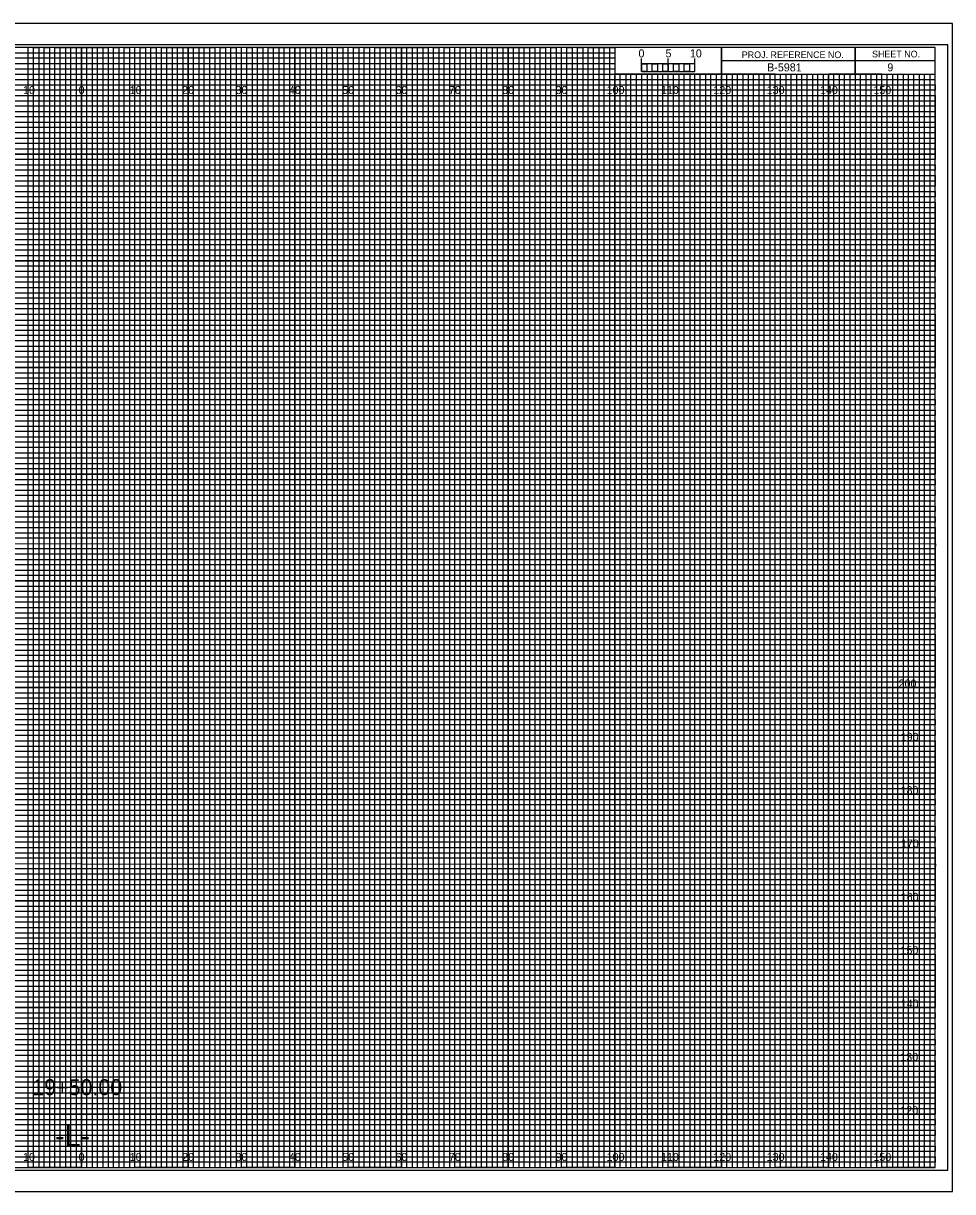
# Model space of a CAD drawing. Extents: x -13 to 323, y -5 to 1754.
# Drawn here: x 149.1 to 323.3, y 1095.5 to 1314.5 of the extents above; entities that cross this region are included whole.
import ezdxf

# ---------------------------------------------------------------- set-up
doc = ezdxf.new("R2010")
doc.units = 0
for name, color, linetype in [('Exist Cross Section Cell', 7, 'Continuous'), ('Exist XS Center Line Elevation Label', 7, 'Continuous'), ('Exist XS Ground Line', 7, 'Continuous'), ('Prop CMT Concrete Structures', 7, 'Continuous'), ('Prop CMT Guardrail Graphics', 7, 'Continuous'), ('Prop CMT Pvmt Course 1', 7, 'Continuous'), ('Prop CMT Pvmt Course 2', 7, 'Continuous'), ('Prop CMT Pvmt Course 3', 7, 'Continuous'), ('Prop CMT Pvmt Surface', 7, 'Continuous'), ('Prop CMT Shld Paved Course 1', 7, 'Continuous'), ('Prop CMT Shld Paved Course 2', 7, 'Continuous'), ('Prop CMT Shld Paved Course 3', 7, 'Continuous'), ('Prop CMT Subgrade Earthwork', 7, 'Continuous'), ('Prop XS Ditch Standard Text', 7, 'Continuous'), ('Prop XS SE Text', 7, 'Continuous'), ('Prop XS Side Slope Text', 7, 'Continuous'), ('Scratch_Level_0', 7, 'Continuous')]:
    doc.layers.add(name, color=color, linetype=linetype)

msp = doc.modelspace()

# ---------------------------------------------------------------- linework, layer by layer
at = {"layer": 'Exist XS Center Line Elevation Label'}
for points in [[(145, 1100), (155, 1100), (155, 1310), (165, 1310), (165, 1100), (175, 1100), (175, 1310), (185, 1310), (185, 1100), (195, 1100), (195, 1310), (205, 1310), (205, 1100), (215, 1100), (215, 1310), (225, 1310), (225, 1100), (235, 1100), (235, 1310), (245, 1310), (245, 1100), (255, 1100), (255, 1310), (259.93, 1310), (260, 1310), (260, 1305), (264.99, 1305), (264.99, 1100), (275, 1100), (275, 1305), (285, 1305), (285, 1100), (295, 1100), (295, 1305), (305, 1305), (305, 1100), (315, 1100), (315, 1305)], [(0, 1305), (275, 1305)], [(0, 1285), (320, 1285), (320, 1295), (0, 1295)], [(0, 1265), (320, 1265), (320, 1275), (0, 1275)], [(0, 1245), (320, 1245), (320, 1255), (0, 1255)], [(0, 1225), (320, 1225), (320, 1235), (0, 1235)], [(0, 1205), (320, 1205), (320, 1215), (0, 1215)], [(0, 1185), (320, 1185), (320, 1195), (0, 1195)], [(0, 1165), (320, 1165), (320, 1175), (0, 1175)], [(0, 1145), (320, 1145), (320, 1155), (0, 1155)], [(0, 1125), (320, 1125), (320, 1135), (0, 1135)], [(0, 1105), (320, 1105), (320, 1115), (0, 1115)]]:
    msp.add_lwpolyline(points, dxfattribs=at)
at = {"layer": 'Exist XS Ground Line'}
for p, q in [((150, 1310), (140, 1310)), ((150, 1100), (150, 1310)), ((170, 1310), (160, 1310)), ((160, 1310), (160, 1100)), ((170, 1100), (170, 1310)), ((190, 1310), (180, 1310)), ((180, 1310), (180, 1100)), ((190, 1100), (190, 1310)), ((210, 1310), (200, 1310)), ((200, 1310), (200, 1100)), ((210, 1100), (210, 1310)), ((230, 1310), (220, 1310)), ((220, 1310), (220, 1100)), ((230, 1100), (230, 1310)), ((250, 1310), (240, 1310)), ((240, 1310), (240, 1100)), ((250, 1100), (250, 1310)), ((260, 1310), (260, 1100)), ((270, 1100), (270, 1305)), ((290, 1305), (280, 1305)), ((280, 1305), (280, 1100)), ((290, 1100), (290, 1305)), ((310, 1305), (300, 1305)), ((300, 1305), (300, 1100)), ((310, 1100), (310, 1305)), ((160, 1100), (150, 1100)), ((180, 1100), (170, 1100)), ((200, 1100), (190, 1100)), ((220, 1100), (210, 1100)), ((240, 1100), (230, 1100)), ((260, 1100), (250, 1100)), ((280, 1100), (270, 1100)), ((300, 1100), (290, 1100)), ((320, 1100), (310, 1100)), ((320, 1100), (320, 1100))]:
    msp.add_line(p, q, dxfattribs=at)
for points in [[(0, 1300), (320, 1300), (320, 1290), (0, 1290)], [(0, 1280), (320, 1280), (320, 1270), (0, 1270)], [(0, 1260), (320, 1260), (320, 1250), (0, 1250)], [(0, 1240), (320, 1240), (320, 1230), (0, 1230)], [(0, 1220), (320, 1220), (320, 1210), (0, 1210)], [(0, 1200), (320, 1200), (320, 1190), (0, 1190)], [(0, 1180), (320, 1180), (320, 1170), (0, 1170)], [(0, 1160), (320, 1160), (320, 1150), (0, 1150)], [(0, 1140), (320, 1140), (320, 1130), (0, 1130)], [(0, 1120), (320, 1120), (320, 1110), (0, 1110)]]:
    msp.add_lwpolyline(points, dxfattribs=at)
at = {"layer": 'Prop CMT Pvmt Course 1'}
for p, q in [((323.3, 1314.5), (-13.4, 1314.5)), ((-13.4, 1095.5), (323.3, 1095.5))]:
    msp.add_line(p, q, dxfattribs=at)
at = {"layer": 'Prop CMT Pvmt Course 2'}
msp.add_lwpolyline([(-13.4, 1095.5), (323.3, 1095.5), (323.3, 1314.5), (-13.4, 1314.5)], close=True, dxfattribs=at)
at = {"layer": 'Prop CMT Pvmt Course 3'}
msp.add_lwpolyline([(-10.8, 1099.5), (322.4, 1099.5), (322.4, 1310.5), (-10.8, 1310.5)], close=True, dxfattribs=at)
at = {"layer": 'Prop CMT Shld Paved Course 1'}
for p, q in [((305, 1310), (305, 1305)), ((305, 1305), (305, 1310)), ((280, 1307.5), (280, 1305)), ((320, 1307.49), (280, 1307.49)), ((280, 1305), (320, 1305))]:
    msp.add_line(p, q, dxfattribs=at)
for points in [[(320, 1310), (0, 1310), (0, 1100), (320, 1100)], [(280, 1310), (260, 1310), (260, 1305.03), (280, 1305.03)], [(320, 1310), (280, 1310), (280, 1305), (320, 1305)]]:
    msp.add_lwpolyline(points, close=True, dxfattribs=at)
at = {"layer": 'Prop CMT Shld Paved Course 2'}
for p, q in [((267, 1305), (266.01, 1305)), ((266.01, 1305), (266.01, 1100)), ((267, 1100), (267, 1305)), ((269, 1305), (268, 1305)), ((268, 1305), (268, 1100)), ((269, 1100), (269, 1305)), ((266.01, 1100), (265, 1100)), ((268, 1100), (267, 1100))]:
    msp.add_line(p, q, dxfattribs=at)
for points in [[(150, 1100), (151, 1100), (151, 1310), (152, 1310), (152, 1100)], [(152, 1100), (153, 1100), (153, 1310), (154, 1310), (154, 1100)], [(155, 1100), (156, 1100), (156, 1310), (157, 1310), (157, 1100)], [(157, 1100), (158, 1100), (158, 1310), (159, 1310), (159, 1100)], [(160, 1100), (161, 1100), (161, 1310), (162, 1310), (162, 1100)], [(162, 1100), (163, 1100), (163, 1310), (164, 1310), (164, 1100)], [(165, 1100), (166, 1100), (166, 1310), (167, 1310), (167, 1100)], [(167, 1100), (168, 1100), (168, 1310), (169, 1310), (169, 1100)], [(170, 1100), (171, 1100), (171, 1310), (172, 1310), (172, 1100)], [(172, 1100), (173, 1100), (173, 1310), (174, 1310), (174, 1100)], [(175, 1100), (176, 1100), (176, 1310), (177, 1310), (177, 1100)], [(177, 1100), (178, 1100), (178, 1310), (179, 1310), (179, 1100)], [(180, 1100), (181, 1100), (181, 1310), (182, 1310), (182, 1100)], [(182, 1100), (183, 1100), (183, 1310), (184, 1310), (184, 1100)], [(185, 1100), (186, 1100), (186, 1310), (187, 1310), (187, 1100)], [(187, 1100), (188, 1100), (188, 1310), (189, 1310), (189, 1100)], [(190, 1100), (191, 1100), (191, 1310), (192, 1310), (192, 1100)], [(192, 1100), (193, 1100), (193, 1310), (194, 1310), (194, 1100)], [(195, 1100), (196, 1100), (196, 1310), (197, 1310), (197, 1100)], [(197, 1100), (198, 1100), (198, 1310), (199, 1310), (199, 1100)], [(200, 1100), (201, 1100), (201, 1310), (202, 1310), (202, 1100)], [(202, 1100), (203, 1100), (203, 1310), (204, 1310), (204, 1100)], [(205, 1100), (206, 1100), (206, 1310), (207, 1310), (207, 1100)], [(207, 1100), (208, 1100), (208, 1310), (209, 1310), (209, 1100)], [(210, 1100), (211, 1100), (211, 1310), (212, 1310), (212, 1100)], [(212, 1100), (213, 1100), (213, 1310), (214, 1310), (214, 1100)], [(215, 1100), (216, 1100), (216, 1310), (217, 1310), (217, 1100)], [(217, 1100), (218, 1100), (218, 1310), (219, 1310), (219, 1100)], [(220, 1100), (221, 1100), (221, 1310), (222, 1310), (222, 1100)], [(222, 1100), (223, 1100), (223, 1310), (224, 1310), (224, 1100)], [(225, 1100), (226, 1100), (226, 1310), (227, 1310), (227, 1100)], [(227, 1100), (228, 1100), (228, 1310), (229, 1310), (229, 1100)], [(230, 1100), (231, 1100), (231, 1310), (232, 1310), (232, 1100)], [(232, 1100), (233, 1100), (233, 1310), (234, 1310), (234, 1100)], [(235, 1100), (236, 1100), (236, 1310), (237, 1310), (237, 1100)], [(237, 1100), (238, 1100), (238, 1310), (239, 1310), (239, 1100)], [(240, 1100), (241, 1100), (241, 1310), (242, 1310), (242, 1100)], [(242, 1100), (243, 1100), (243, 1310), (244, 1310), (244, 1100)], [(245, 1100), (246, 1100), (246, 1310), (247, 1310), (247, 1100)], [(247, 1100), (248, 1100), (248, 1310), (249, 1310), (249, 1100)], [(250, 1100), (251, 1100), (251, 1310), (252, 1310), (252, 1100)], [(252, 1100), (253, 1100), (253, 1310), (254, 1310), (254, 1100)], [(255, 1100), (256, 1100), (256, 1310), (257, 1310), (257, 1100)], [(257, 1100), (258, 1100), (258, 1310), (259, 1310), (259, 1100)], [(260, 1100), (261, 1100), (261, 1305), (262.02, 1305), (262.02, 1100)], [(262, 1100), (263, 1100), (263, 1305), (263.99, 1305), (263.99, 1100)], [(270, 1100), (270.98, 1100), (270.98, 1305), (272, 1305), (272, 1100)], [(272, 1100), (273, 1100), (273, 1305), (274.05, 1305), (274.05, 1100)], [(275, 1100), (276, 1100), (276, 1305), (277, 1305), (277, 1100)], [(277, 1100), (278, 1100), (278, 1305), (279, 1305), (279, 1100)], [(280, 1100), (281, 1100), (281, 1305), (282, 1305), (282, 1100)], [(282, 1100), (283, 1100), (283, 1305), (284, 1305), (284, 1100)], [(285, 1100), (286, 1100), (286, 1305), (287, 1305), (287, 1100)], [(287, 1100), (288, 1100), (288, 1305), (289, 1305), (289, 1100)], [(290, 1100), (291, 1100), (291, 1305), (292, 1305), (292, 1100)], [(292, 1100), (293, 1100), (293, 1305), (294, 1305), (294, 1100)], [(295, 1100), (296, 1100), (296, 1305), (297, 1305), (297, 1100)], [(297, 1100), (298, 1100), (298, 1305), (299, 1305), (299, 1100)], [(300, 1100), (301, 1100), (301, 1305), (302, 1305), (302, 1100)], [(302, 1100), (303, 1100), (303, 1305), (304, 1305), (304, 1100)], [(305, 1100), (306, 1100), (306, 1305), (307, 1305), (307, 1100)], [(307, 1100), (308, 1100), (308, 1305), (309, 1305), (309, 1100)], [(310, 1100), (311, 1100), (311, 1305), (312, 1305), (312, 1100)], [(312, 1100), (313, 1100), (313, 1305), (314, 1305), (314, 1100)], [(315, 1100), (316, 1100), (316, 1305), (317, 1305), (317, 1100)], [(317, 1100), (318, 1100), (318, 1305), (319, 1305), (319, 1100)]]:
    msp.add_lwpolyline(points, dxfattribs=at)
at = {"layer": 'Prop CMT Shld Paved Course 3'}
for p, q in [((265, 1305.49), (265, 1307.9)), ((265, 1306.9), (265, 1307.9)), ((270, 1305.49), (270, 1307.9)), ((275, 1305.49), (275, 1307.9)), ((275, 1306.9), (275, 1307.9))]:
    msp.add_line(p, q, dxfattribs=at)
for points in [[(275, 1306.9), (265, 1306.9), (265, 1305.49), (275, 1305.49)], [(265, 1306.9), (266, 1306.9), (266, 1305.49), (265, 1305.49)], [(267, 1306.9), (268, 1306.9), (268, 1305.49), (267, 1305.49)], [(269, 1306.9), (270, 1306.9), (270, 1305.49), (269, 1305.49)], [(271, 1306.9), (272, 1306.9), (272, 1305.49), (271, 1305.49)], [(273, 1306.9), (274, 1306.9), (274, 1305.49), (273, 1305.49)]]:
    msp.add_lwpolyline(points, close=True, dxfattribs=at)
at = {"layer": 'Prop CMT Subgrade Earthwork'}
for p, q in [((150, 1100), (150, 1310)), ((160, 1100), (160, 1310)), ((170, 1100), (170, 1310)), ((180, 1100), (180, 1310)), ((190, 1100), (190, 1310)), ((200, 1100), (200, 1310)), ((210, 1100), (210, 1310)), ((220, 1100), (220, 1310)), ((230, 1100), (230, 1310)), ((240, 1100), (240, 1310)), ((250, 1100), (250, 1310)), ((260, 1100), (260, 1304.69)), ((270, 1100), (270, 1304.69)), ((280, 1100), (280, 1304.69)), ((290, 1100), (290, 1304.69)), ((300, 1100), (300, 1304.69)), ((310, 1100), (310, 1304.69)), ((0, 1300), (320, 1300)), ((0, 1290), (320, 1290)), ((0, 1280), (320, 1280)), ((0, 1270), (320, 1270)), ((0, 1260), (320, 1260)), ((0, 1250), (320, 1250)), ((0, 1240), (320, 1240)), ((0, 1230), (320, 1230)), ((0, 1220), (320, 1220)), ((0, 1210), (320, 1210)), ((0, 1200), (320, 1200)), ((0, 1190), (320, 1190)), ((0, 1180), (320, 1180)), ((0, 1170), (320, 1170)), ((0, 1160), (320, 1160)), ((0, 1150), (320, 1150)), ((0, 1140), (320, 1140)), ((0, 1130), (320, 1130)), ((0, 1120), (320, 1120)), ((0, 1110), (320, 1110))]:
    msp.add_line(p, q, dxfattribs=at)
at = {"layer": 'Scratch_Level_0'}
for p, q in [((0, 1309), (260, 1309)), ((260, 1307.98), (0, 1307.98)), ((260, 1309), (260, 1307.98)), ((0, 1307), (260, 1307)), ((260, 1305.89), (0, 1305.89)), ((260, 1307), (260, 1305.89)), ((0, 1304), (320, 1304))]:
    msp.add_line(p, q, dxfattribs=at)
for points in [[(0, 1303), (270, 1303), (320, 1303), (320, 1302), (0, 1302)], [(0, 1301), (320, 1301), (320, 1299), (0, 1299)], [(0, 1298), (320, 1298), (320, 1297), (0, 1296.98)], [(0, 1296), (320, 1296), (320, 1294), (0, 1294)], [(0, 1293), (320, 1293), (320, 1292), (0, 1292)], [(0, 1291), (320, 1291), (320, 1289), (0, 1289)], [(0, 1288), (320, 1288), (320, 1287), (0, 1287)], [(0, 1286), (320, 1286), (320, 1284), (0, 1284)], [(0, 1283), (320, 1283), (320, 1282), (0, 1282)], [(0, 1281), (320, 1281), (320, 1279), (0, 1279)], [(0, 1278), (320, 1278), (320, 1277), (0, 1277)], [(0, 1276), (320, 1276), (320, 1273.95), (320, 1273), (320, 1272), (0, 1272)], [(0, 1274), (320, 1274), (320, 1273), (0, 1273)], [(0, 1271), (320, 1271), (320, 1269), (0, 1269.03)], [(0, 1269.03), (320, 1269), (320, 1268), (0, 1268)], [(0, 1267), (320, 1267), (320, 1266), (0, 1266)], [(0, 1264), (320, 1264), (320, 1263), (0, 1263)], [(0, 1262), (320, 1262), (320, 1261), (0, 1261)], [(-0.07, 1258.89), (320, 1258.89), (320, 1257.88), (-0.07, 1257.88)], [(0, 1257), (320, 1257), (320, 1256), (0, 1256)], [(0, 1254), (320, 1254), (320, 1253), (0, 1253)], [(0, 1252), (320, 1252), (320, 1251), (0, 1251)], [(0, 1249), (320, 1249), (320, 1248), (0, 1248)], [(0, 1247), (320, 1247), (320, 1246), (0, 1246)], [(0, 1244), (320, 1244), (320, 1243), (0, 1243)], [(0, 1242), (320, 1242), (320, 1241), (0, 1241)], [(0, 1239), (320, 1239), (319.99, 1237.98), (0, 1238)], [(0, 1237), (320, 1237), (320, 1236), (0, 1236)], [(0, 1234), (320, 1234), (320, 1233), (0, 1233)], [(0, 1232), (320, 1232), (320, 1231), (0, 1231)], [(0, 1229), (320, 1229), (320, 1228), (0, 1228)], [(0, 1227), (320, 1227), (320, 1226), (0, 1226)], [(0, 1224), (320, 1224), (320, 1223), (0, 1223)], [(0, 1222), (320, 1222), (320, 1221), (0, 1221)], [(0, 1219), (320, 1219), (320, 1218), (0, 1218)], [(0, 1216.99), (320.07, 1216.91), (320, 1216), (0, 1216)], [(0, 1214), (320, 1214), (320, 1213), (0, 1213)], [(0, 1212), (320, 1212), (320, 1211), (0, 1211)], [(0, 1209), (320, 1209), (320, 1208), (0, 1208)], [(0, 1207), (320, 1207), (320, 1206), (0, 1206)], [(0, 1204), (320, 1204), (320, 1203), (0, 1203)], [(0, 1202), (320, 1202), (320, 1201), (0, 1201)], [(0, 1199), (320, 1199), (320, 1198), (0, 1198)], [(0, 1197), (320, 1197), (320, 1196), (0, 1196)], [(0, 1194), (320, 1194), (320, 1193), (0, 1193)], [(0, 1192), (320, 1192), (320, 1191), (0, 1191)], [(0, 1189), (320, 1189), (320, 1188), (0, 1188)], [(0, 1187), (320, 1187), (320, 1186), (0, 1186)], [(0, 1184), (320, 1184), (320, 1183), (0, 1183)], [(0, 1182), (320, 1182), (320, 1181), (0, 1181)], [(0, 1179), (320, 1179), (319.99, 1177.98), (0, 1178)], [(0, 1177), (320, 1177), (320, 1176), (0, 1176)], [(0, 1174), (320, 1174), (320, 1173), (0, 1173)], [(0, 1172), (320, 1172), (320, 1171), (0, 1171)], [(0, 1169), (320, 1169), (320, 1168), (0, 1168)], [(0, 1167), (320, 1167), (320, 1166), (0, 1166)], [(0, 1164), (320, 1164), (320, 1163), (0, 1163)], [(0, 1162), (320, 1162), (320, 1161), (0, 1161)], [(0, 1159), (320, 1159), (320, 1158), (0, 1158)], [(0, 1156.99), (320.07, 1156.91), (320, 1156), (0, 1156)], [(0, 1154), (320, 1154), (320, 1153), (0, 1153)], [(0, 1152), (320, 1152), (320, 1151), (0, 1151)], [(0, 1149), (320, 1149), (320, 1148), (0, 1148)], [(0, 1147), (320, 1147), (320, 1146), (0, 1146)], [(0, 1144), (320, 1144), (320, 1143), (0, 1143)], [(0, 1142), (320, 1142), (320, 1141), (0, 1141)], [(0, 1139), (320, 1139), (320, 1138), (0, 1138)], [(0, 1137), (320, 1137), (320, 1136), (0, 1136)], [(0, 1134), (320, 1134), (320, 1133), (0, 1133)], [(0, 1132), (320, 1132), (320, 1131), (0, 1131)], [(0, 1129), (320, 1129), (320, 1128), (0, 1128)], [(0, 1127), (320, 1127), (320, 1126), (0, 1126)], [(0, 1124), (320, 1124), (320, 1123), (0, 1123)], [(0, 1122), (320, 1122), (320, 1121), (0, 1121)], [(0, 1119), (320, 1119), (320, 1118), (0, 1118)], [(0, 1117), (320, 1117), (320, 1116), (0, 1116)], [(0, 1114), (320, 1114), (320, 1113), (0, 1113)], [(0, 1112), (320, 1112), (320, 1111), (0, 1111)], [(0, 1109), (320, 1109), (320, 1108), (0, 1108)], [(0, 1107), (320, 1107), (320, 1106), (0, 1106)], [(0, 1104), (320, 1104), (320, 1103), (0, 1103)], [(0, 1102), (320, 1102), (320, 1101), (0, 1101)]]:
    msp.add_lwpolyline(points, dxfattribs=at)

# ---------------------------------------------------------------- texts
at = {"layer": 'Exist Cross Section Cell'}
for s, p in [('200', (313.17, 1190)), ('190', (313.57, 1180)), ('180', (313.55, 1170)), ('170', (313.61, 1160)), ('160', (313.57, 1150)), ('150', (313.52, 1140)), ('140', (313.57, 1130)), ('130', (313.49, 1120)), ('120', (313.5, 1110))]:
    msp.add_text(s, height=1.5, dxfattribs=at).set_placement(p)
at = {"layer": 'Prop CMT Concrete Structures'}
msp.add_text('9', height=1.5, dxfattribs=at).set_placement((311.06, 1305.5))
at = {"layer": 'Prop CMT Guardrail Graphics'}
for s, p in [('5', (269.47, 1308.12)), ('10', (274.04, 1308.12))]:
    msp.add_text(s, height=1.5, dxfattribs=at).set_placement(p)
at = {"layer": 'Prop CMT Pvmt Surface'}
msp.add_text('19+50.00', height=3, dxfattribs=at).set_placement((150.77, 1113.58))
at = {"layer": 'Prop CMT Shld Paved Course 1'}
for s, p in [('PROJ. REFERENCE NO.', (283.77, 1307.99)), ('SHEET NO.', (308.19, 1308.12))]:
    msp.add_text(s, height=1.25, dxfattribs=at).set_placement(p)
at = {"layer": 'Prop CMT Shld Paved Course 3'}
msp.add_text('0', height=1.5, dxfattribs=at).set_placement((264.41, 1308.12))
at = {"layer": 'Prop XS Ditch Standard Text'}
for s, p in [('10', (149.04, 1301.25)), ('0', (159.45, 1301.25)), ('0', (159.45, 1301.25)), ('10', (169.04, 1301.25)), ('20', (178.86, 1301.25)), ('30', (188.86, 1301.25)), ('40', (198.86, 1301.25)), ('50', (208.86, 1301.25)), ('60', (218.86, 1301.25)), ('70', (228.86, 1301.25)), ('80', (238.86, 1301.25)), ('90', (248.86, 1301.25)), ('100', (258.44, 1301.25)), ('110', (268.62, 1301.25)), ('120', (278.44, 1301.25)), ('130', (288.44, 1301.25)), ('140', (298.44, 1301.25)), ('150', (308.44, 1301.25)), ('10', (149.04, 1101.25)), ('0', (159.45, 1101.25)), ('0', (159.45, 1101.25)), ('10', (169.04, 1101.25)), ('20', (178.86, 1101.25)), ('30', (188.86, 1101.25)), ('40', (198.86, 1101.25)), ('50', (208.86, 1101.25)), ('60', (218.86, 1101.25)), ('70', (228.86, 1101.25)), ('80', (238.86, 1101.25)), ('90', (248.86, 1101.25)), ('100', (258.44, 1101.25)), ('110', (268.62, 1101.25)), ('120', (278.44, 1101.25)), ('130', (288.44, 1101.25)), ('140', (298.44, 1101.25)), ('150', (308.44, 1101.25))]:
    msp.add_text(s, height=1.5, dxfattribs=at).set_placement(p)
at = {"layer": 'Prop XS SE Text'}
msp.add_text('-L-', height=4, dxfattribs=at).set_placement((155.06, 1104))
at = {"layer": 'Prop XS Side Slope Text'}
msp.add_text('B-5981', height=1.5, dxfattribs=at).set_placement((288.53, 1305.5))

doc.saveas('drawing.dxf')
